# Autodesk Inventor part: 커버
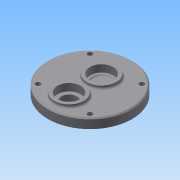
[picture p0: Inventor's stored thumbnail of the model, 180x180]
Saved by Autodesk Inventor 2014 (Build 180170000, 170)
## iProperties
Created: 2015-06
Part Number: 커버
Material: 일반
Document SubType Name: Modeling
Designer: AMC
Density: 1 g/cm^3
Appearance: 기본값
Author: AMC
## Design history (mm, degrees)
sketch "스케치1"
  geometry: C1 r 40 at (0, 0); 1 further point
  constraints: 1 centre point, 1 coincident
  dimensions: "d0" = 80 diameter of C1
extrude "돌출1" new body sketch "스케치1" distance "d1" = 9; taper "d2" = 0 deg
sketch "스케치5"
  geometry: C1 r 40 at (0, 0) reference; C2 r 14 at (0, 11); C3 r 14 at (0, -20)
  constraints: 2 centre point
  dimensions: "d21" = 28 diameter of C3; "d22" = 28 diameter of C2; "d23" = 0 horizontal distance of C1.centre C2.centre; "d24" = 11 distance of C1.centre C2.centre; "d25" = 0 horizontal distance of C1.centre C3.centre; "d26" = 20 distance of C1.centre C3.centre
extrude "돌출4" join sketch "스케치5" distance "d27" = 3; taper "d28" = 0 deg
sketch "스케치6"
  geometry: C1 r 40 at (0, 0) reference; C2 r 14 at (0, -20)
  constraints: 1 centre point
  dimensions: "d29" = 28 diameter of C2; "d30" = 0 horizontal distance of C1.centre C2.centre; "d31" = 20 distance of C1.centre C2.centre
extrude "돌출5" join sketch "스케치6" distance "d32" = 4; taper "d33" = 0 deg
sketch "스케치7"
  geometry: L1 (40, 9)-(40, 0) reference; L2 (40, 0)-(-6, 0) reference; L3 (-6, 0)-(-6, -4) reference; L4 (-6, -4)-(-34, -4) reference; L5 (-34, -4)-(-34, 0) reference; L6 (-34, 0)-(-40, 0) reference; L7 (-40, 0)-(-40, 9) reference; L8 (-40, 9)-(-34, 9) reference; L9 (-34, 9)-(-34, 12) reference; L10 (-34, 12)-(-6, 12) reference; L11 (-6, 12)-(-6, 9) reference; L12 (-6, 9)-(-3, 9) reference; L13 (-3, 9)-(-3, 12) reference; L14 (-3, 12)-(25, 12) reference; L15 (25, 12)-(25, 9) reference; L16 (25, 9)-(40, 9) reference; L17 (-20, -4)-(-20, 12); L18 (-9, -4)-(-9, 3); L19 (-9, 3)-(-12.5, 3); L20 (-12.5, 3)-(-12.5, 5); L21 (-12.5, 5)-(-9, 5); L22 (-9, 5)-(-9, 12); L23 (11, 12)-(11, 4); L24 (11, 4)-(20, 4); L25 (20, 4)-(20, 5); L26 (20, 5)-(22, 5); L27 (22, 5)-(22, 12); 1 further point
  constraints: 22 end point, 6 perpendicular, 4 parallel, 3 midpoint, 3 point on line
  dimensions: "d34" = 22 diameter of L22 L17; "d35" = 15 diameter of L20 L17; "d36" = 22 diameter of L18 L17; "d37" = 7 distance between parallel lines of L4 L19; "d38" = 2 distance between parallel lines of L21 L19; "d39" = 22 diameter of L27 L23; "d40" = 18 diameter of L25 L23; "d41" = 1 distance between parallel lines of L26 L24; "d42" = 7 distance between parallel lines of L14 L26
  node "절단 모서리 투영2"
revolve "회전1" stored, may be unused: angle "d43" = 90 deg
revolve "회전2" stored, may be unused: angle "d44" = 90 deg
sketch "스케치8"
  geometry: L1 (0, 0)-(-24.749, 24.749); L2 (0, 0)-(35, 0); C1 r 40 at (0, 0) reference
  constraints: 4 end point, 1 equal length, 1 horizontal
  dimensions: "d45" = 35 distance of L1.start L1.end; "d46" = 135 deg angle of L2 L1
hole "구멍1" sketch "스케치8" at (-24.749, 24.749) diameter "d47" = 4.5; stored, may be unused: countersink angle "d51" = 90 deg, drill point angle "d53" = 118 deg; dims "d48" = 6, "d49" = 8, "d50" = 4.4, "d52" = 8
fillet "모깎기1" dims "d57" = 0.3
fillet "모깎기2" dims "d58" = 2
chamfer "모따기1" distance "d59" = 1; stored, may be unused: second distance "d60" = 2, angle "d61" = 45 deg
fillet "모깎기3" dims "d62" = 2
node "솔리드1"
pattern_circular "원형 패턴1" dims angle "d55" = 360 deg
